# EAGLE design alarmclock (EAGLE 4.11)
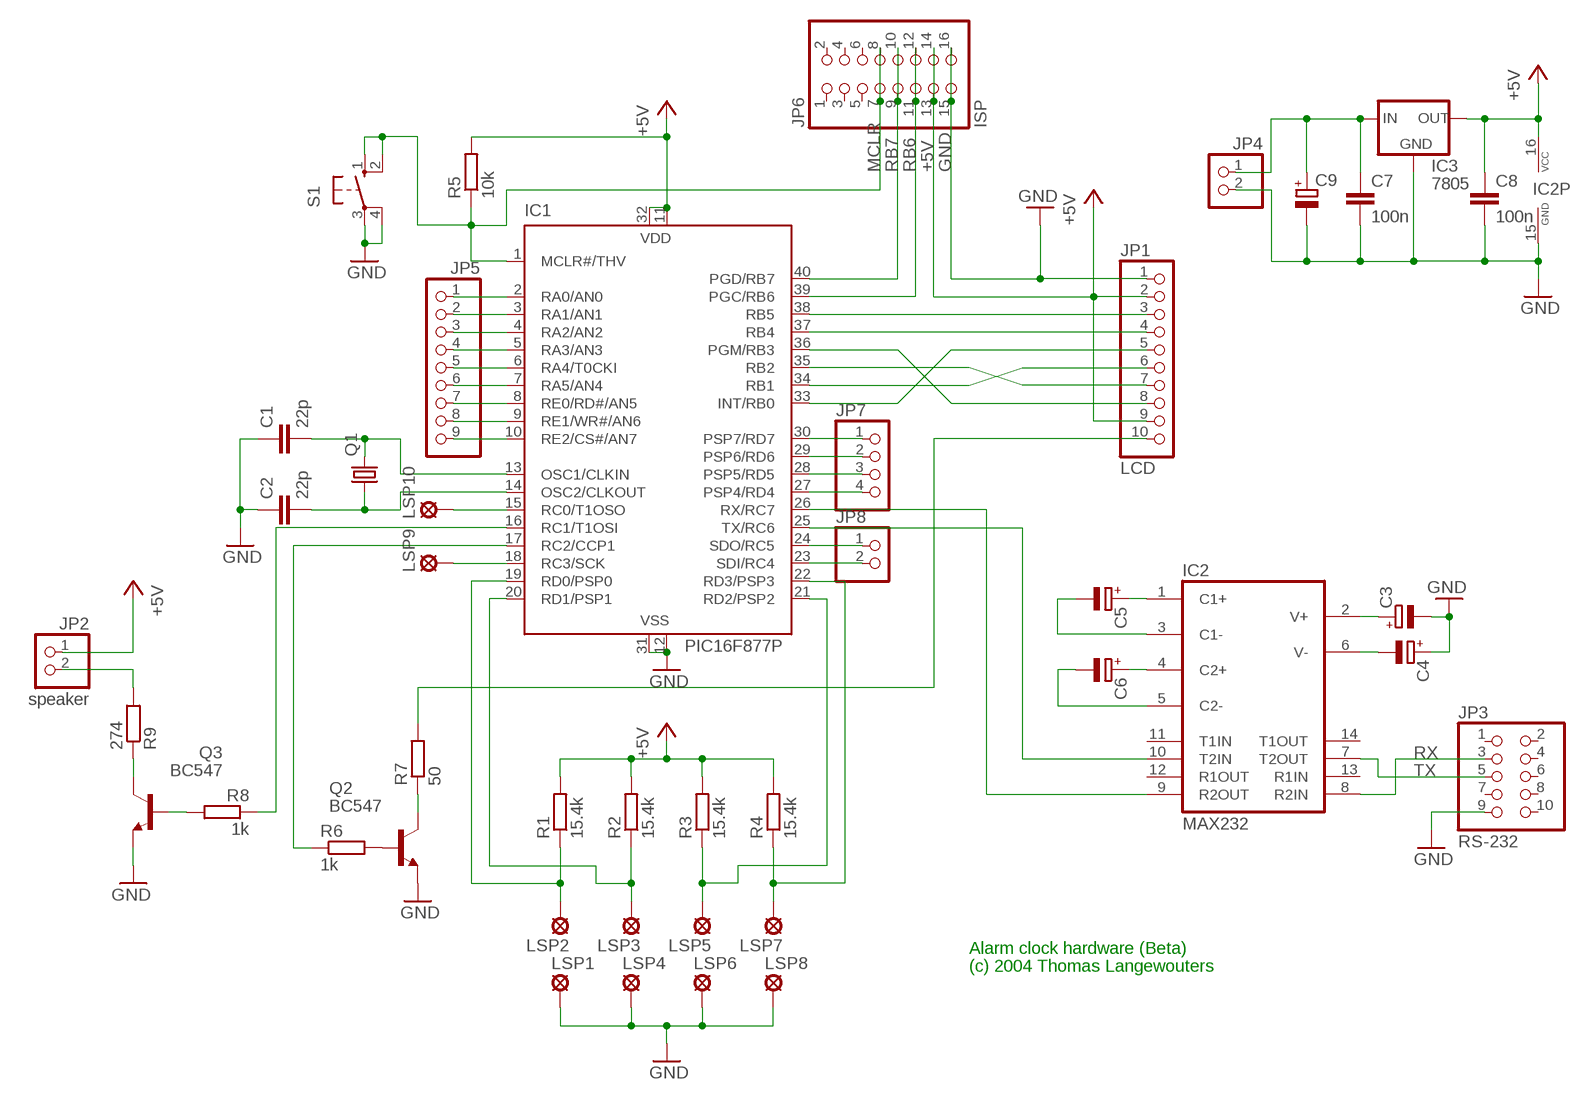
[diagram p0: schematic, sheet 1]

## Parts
C1  22p  C-EU050-025X075  [C050-025X075]
C2  22p  C-EU050-025X075  [C050-025X075]
C3  CPOL-EUE5-5  [E5-5]
C4  CPOL-EUE5-5  [E5-5]
C5  CPOL-EUE5-5  [E5-5]
C6  CPOL-EUE5-5  [E5-5]
C7  100n  C-EU050-030X075  [C050-030X075]
C8  100n  C-EU050-030X075  [C050-030X075]
C9  CPOL-EUE5-10.5  [E5-10,5]
IC1  PIC16F877P  [DIL40]
IC2  MAX232  [DIL16]
IC3  7805  78XXS  [78XXS]
JP1  LCD  PINHD-1X10  [1X10]
JP2  speaker  PINHD-1X2  [1X02]
JP3  RS-232  PINHD-2X5  [2X05]
JP4  PINHD-1X2  [1X02]
JP5  PINHD-1X9  [1X09]
JP6  ISP  PINHD-2X8  [2X08]
JP7  PINHD-1X4  [1X04]
JP8  PINHD-1X2  [1X02]
LSP1  SE11  [SE11]
LSP2  SE11  [SE11]
LSP3  SE11  [SE11]
LSP4  SE11  [SE11]
LSP5  SE11  [SE11]
LSP6  SE11  [SE11]
LSP7  SE11  [SE11]
LSP8  SE11  [SE11]
LSP9  SE11  [SE11]
LSP10  SE11  [SE11]
Q1  CRYTALHC49S  [HC49/S]
Q2  BC547  [TO92]
Q3  BC547  [TO92]
R1  15.4k  R-EU_0207/10  [0207/10]
R2  15.4k  R-EU_0207/10  [0207/10]
R3  15.4k  R-EU_0207/10  [0207/10]
R4  15.4k  R-EU_0207/10  [0207/10]
R5  10k  R-EU_0207/10  [0207/10]
R6  1k  R-EU_0207/10  [0207/10]
R7  50  R-EU_0207/10  [0207/10]
R8  1k  R-EU_0207/10  [0207/10]
R9  274  R-EU_0207/10  [0207/10]
S1  10-XX  [B3F-10XX]

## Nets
+5V: C8.1 IC1.11(VDD) IC1.32(VDD) IC2.16(VCC) IC3.OUT JP1.2 JP1.9 JP2.1 JP6.13 JP6.14 R1.2 R2.2 R3.2 R4.2 R5.2
GND: C1.1 C2.1 C3.- C4.+ C7.2 C8.2 C9.- IC1.12(VSS) IC1.31(VSS) IC2.15(GND) IC3.GND JP1.1 JP3.9 JP4.2 JP6.15 JP6.16 LSP1.MP LSP4.MP LSP6.MP LSP8.MP Q2.1(E) Q3.1(E) S1.3(P) S1.4(P1)
MCLR: IC1.1(MCLR#/THV) JP6.7 JP6.8 R5.1 S1.1(S) S1.2(S1)
N$1: C1.2 IC1.13(OSC1/CLKIN) Q1.2
N$3: IC1.36(PGM/RB3) JP1.8
N$4: IC1.19(RD0/PSP0) LSP2.MP R1.1
N$5: IC1.20(RD1/PSP1) LSP3.MP R2.1
N$6: IC1.21(RD2/PSP2) LSP5.MP R3.1
N$7: IC1.22(RD3/PSP3) LSP7.MP R4.1
N$8: IC1.33(INT/RB0) JP1.5
N$9: IC1.34(RB1) JP1.6
N$10: IC1.35(RB2) JP1.7
N$11: IC1.25(TX/RC6) IC2.10(T2IN)
N$12: IC1.26(RX/RC7) IC2.9(R2OUT)
N$13: C6.- IC2.5(C2-)
N$14: IC1.17(RC2/CCP1) R6.1
N$15: JP1.10 R7.2
N$16: IC1.38(RB5) JP1.3
N$17: IC1.37(RB4) JP1.4
N$18: Q2.3(C) R7.1
N$19: Q2.2(B) R6.2
N$20: IC1.16(RC1/T1OSI) R8.1
N$21: Q3.2(B) R8.2
N$22: Q3.3(C) R9.1
N$23: JP2.2 R9.2
N$24: C6.+ IC2.4(C2+)
N$25: C5.- IC2.3(C1-)
N$26: C5.+ IC2.1(C1+)
N$27: C4.- IC2.6(V-)
N$28: C3.+ IC2.2(V+)
N$29: C7.1 C9.+ IC3.IN JP4.1
N$32: IC1.2(RA0/AN0) JP5.1
N$33: IC1.3(RA1/AN1) JP5.2
N$34: IC1.4(RA2/AN2) JP5.3
N$35: IC1.5(RA3/AN3) JP5.4
N$36: IC1.6(RA4/T0CKI) JP5.5
N$37: IC1.7(RA5/AN4) JP5.6
N$38: IC1.8(RE0/RD#/AN5) JP5.7
N$39: IC1.9(RE1/WR#/AN6) JP5.8
N$40: IC1.10(RE2/CS#/AN7) JP5.9
N$41: IC1.30(PSP7/RD7) JP7.1
N$42: IC1.29(PSP6/RD6) JP7.2
N$43: IC1.28(PSP5/RD5) JP7.3
N$44: IC1.27(PSP4/RD4) JP7.4
N$45: IC1.24(SDO/RC5) JP8.1
N$46: IC1.23(SDI/RC4) JP8.2
N$47: C2.2 IC1.14(OSC2/CLKOUT) Q1.1
N$52: IC1.15(RC0/T1OSO) LSP10.MP
N$53: IC1.18(RC3/SCK) LSP9.MP
RB6: IC1.39(PGC/RB6) JP6.11 JP6.12
RB7: IC1.40(PGD/RB7) JP6.9 JP6.10
RX: IC2.8(R2IN) JP3.3
TX: IC2.7(T2OUT) JP3.5
Unconnected: IC2.11(T1IN) IC2.12(R1OUT) IC2.13(R1IN) IC2.14(T1OUT) JP3.1 JP3.2 JP3.4 JP3.6 JP3.7 JP3.8 JP3.10 JP6.1 JP6.2 JP6.3 JP6.4 JP6.5 JP6.6

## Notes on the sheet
- Alarm clock hardware (Beta)
- (c) 2004 Thomas Langewouters

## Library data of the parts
C1 C2 C7 C8 = rcl:C-EU: CAPACITOR, European symbol
C3-C6 C9 = rcl:CPOL-EU: POLARIZED CAPACITOR, European symbol
IC1 = microchip:PIC16F87*: MICROCONTROLLER
IC2 = maxim:MAX232: RS232 TRANSEIVER
IC3 = v-reg:78XXS: VOLTAGE REGULATOR
JP1 = pinhead:PINHD-1X10: PIN HEADER
JP2 JP4 JP8 = pinhead:PINHD-1X2: PIN HEADER
JP3 = pinhead:PINHD-2X5: PIN HEADER
JP5 = pinhead:PINHD-1X9: PIN HEADER
JP6 = pinhead:PINHD-2X8: PIN HEADER
JP7 = pinhead:PINHD-1X4: PIN HEADER
LSP1-LSP10 = solpad:SE11: SOLDER PAD
Q1 = crystal:CRYTAL: CRYSTAL
Q2 Q3 = transistor-npn:BC547*: NPN Transistor
R1-R9 = rcl:R-EU_: RESISTOR, European symbol
S1 = switch-omron:10-XX: OMRON SWITCH

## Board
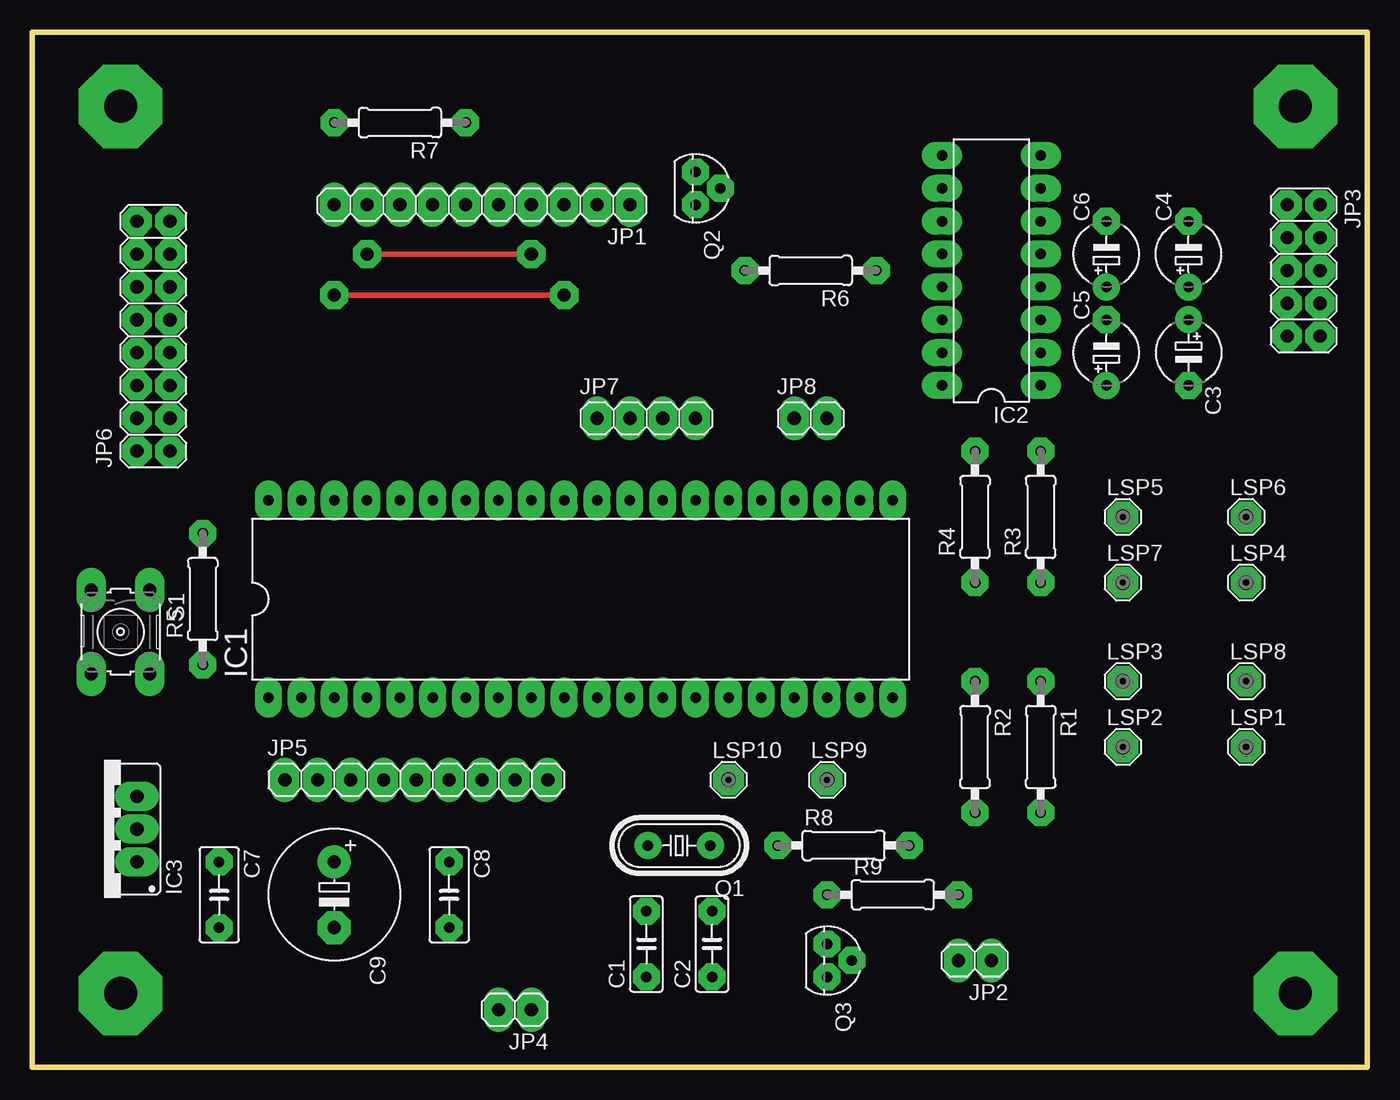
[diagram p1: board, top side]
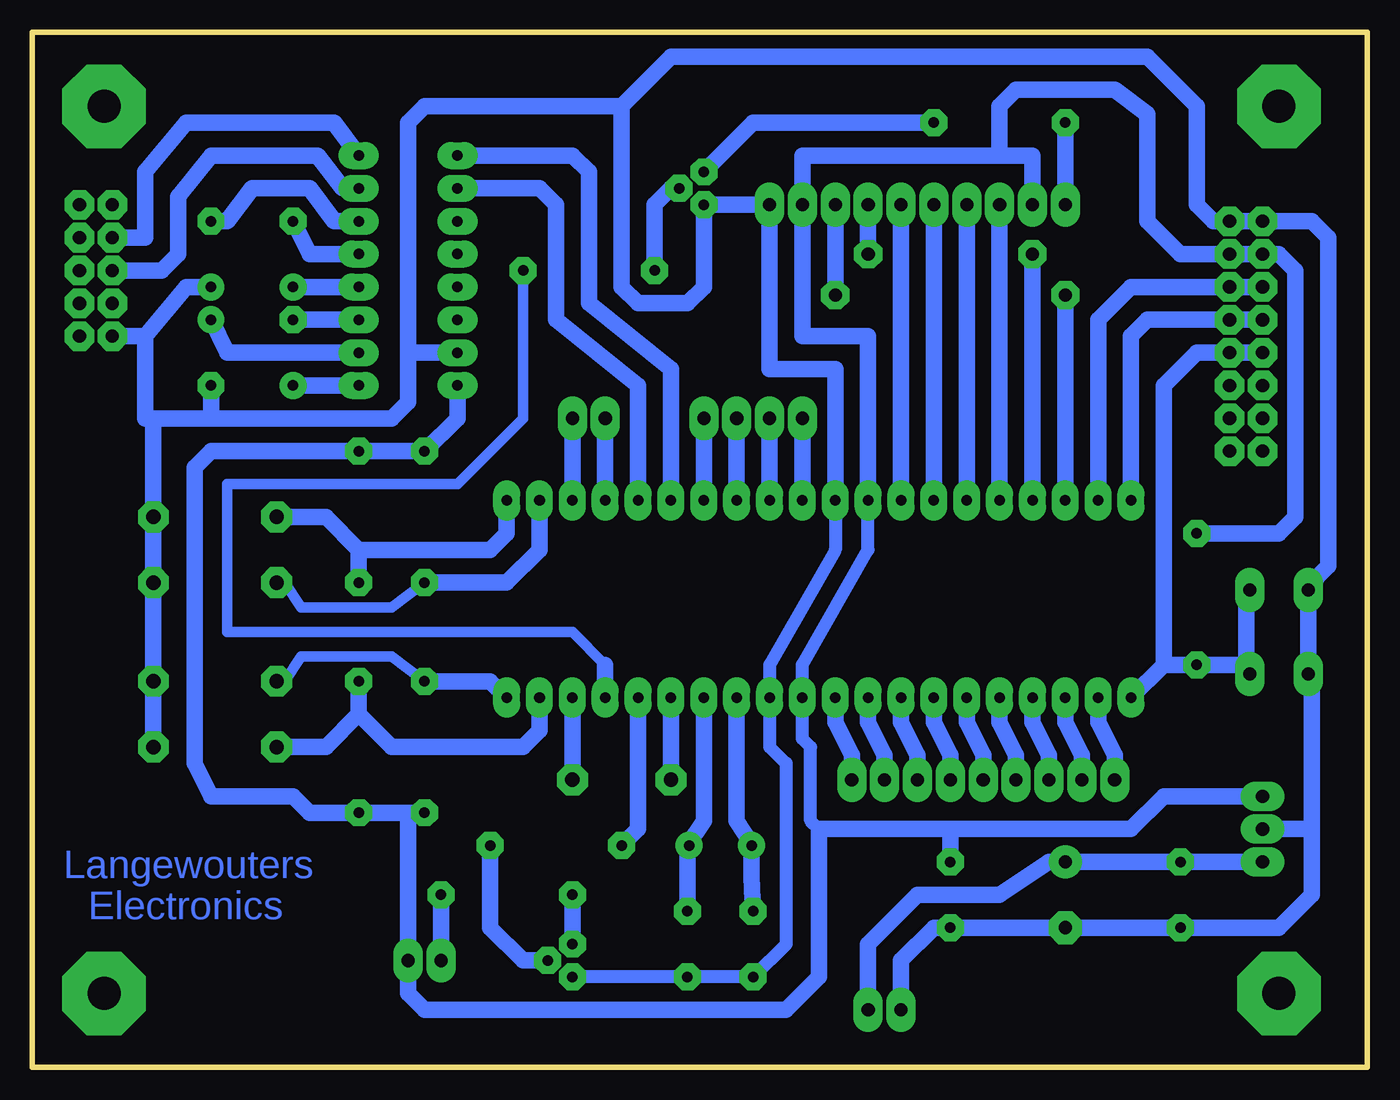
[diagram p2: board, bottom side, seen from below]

Size 103.17 x 80 mm. Coordinates in mm from the lower left corner, seen from the top.
Outline: 0,0 103.17,0 103.17,80 0,80 0,0
Copper layers (1*16): Top 0.035mm / dielectric 1.5mm / Bottom 0.035mm
Design rules "default": minimum track width 10mil, minimum drill 24mil, track to track 10mil, track to pad 8mil, pad to pad 8mil, via to via 8mil, smd to smd 8mil, copper to edge 40mil, drill to drill 8mil, minimum pad ring 15mil, minimum via ring 15mil, stop-mask expansion 4mil, vias tented up to drill 0mil, thermal gap 10mil

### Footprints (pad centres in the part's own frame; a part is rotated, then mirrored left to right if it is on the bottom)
C050-025X075 = drill 0.813 octagon: 1 -2.54,0; 2 2.54,0
E5-5 = drill 0.813 pad 1.905 round: + -2.54,0 | drill 0.813 pad 1.905 octagon: - 2.54,0
C050-030X075 = drill 0.813 octagon: 1 -2.54,0; 2 2.54,0
E5-10,5 = drill 1.016 pad 2.54 round: + -2.54,0 | drill 1.016 pad 2.54 octagon: - 2.54,0
DIL40 = drill 0.813 long: 1 -24.13,-7.62; 2 -21.59,-7.62; 3 -19.05,-7.62; 4 -16.51,-7.62; 5 -13.97,-7.62; 6 -11.43,-7.62; 7 -8.89,-7.62; 8 -6.35,-7.62; 9 -3.81,-7.62; 10 -1.27,-7.62; 11 1.27,-7.62; 12 3.81,-7.62; 13 6.35,-7.62; 14 8.89,-7.62; 15 11.43,-7.62; 16 13.97,-7.62; 17 16.51,-7.62; 18 19.05,-7.62; 19 21.59,-7.62; 20 24.13,-7.62; 21 24.13,7.62; 22 21.59,7.62; 23 19.05,7.62; 24 16.51,7.62; 25 13.97,7.62; 26 11.43,7.62; 27 8.89,7.62; 28 6.35,7.62; 29 3.81,7.62; 30 1.27,7.62; 31 -1.27,7.62; 32 -3.81,7.62; 33 -6.35,7.62; 34 -8.89,7.62; 35 -11.43,7.62; 36 -13.97,7.62; 37 -16.51,7.62; 38 -19.05,7.62; 39 -21.59,7.62; 40 -24.13,7.62
DIL16 = drill 0.813 long: 1 -8.89,-3.81; 2 -6.35,-3.81; 3 -3.81,-3.81; 4 -1.27,-3.81; 5 1.27,-3.81; 6 3.81,-3.81; 7 6.35,-3.81; 8 8.89,-3.81; 9 8.89,3.81; 10 6.35,3.81; 11 3.81,3.81; 12 1.27,3.81; 13 -1.27,3.81; 14 -3.81,3.81; 15 -6.35,3.81; 16 -8.89,3.81
78XXS = drill 1.016 long: GND 0,-2.54; IN -2.54,-2.54; OUT 2.54,-2.54
1X10 = drill 1.016 long: 1 -11.43,0; 2 -8.89,0; 3 -6.35,0; 4 -3.81,0; 5 -1.27,0; 6 1.27,0; 7 3.81,0; 8 6.35,0; 9 8.89,0; 10 11.43,0
1X02 = drill 1.016 long: 1 -1.27,0; 2 1.27,0
2X05 = drill 1.016 octagon: 1 -5.08,-1.27; 2 -5.08,1.27; 3 -2.54,-1.27; 4 -2.54,1.27; 5 0,-1.27; 6 0,1.27; 7 2.54,-1.27; 8 2.54,1.27; 9 5.08,-1.27; 10 5.08,1.27
1X09 = drill 1.016 long: 1 -10.16,0; 2 -7.62,0; 3 -5.08,0; 4 -2.54,0; 5 0,0; 6 2.54,0; 7 5.08,0; 8 7.62,0; 9 10.16,0
2X08 = drill 1.016 octagon: 1 -8.89,-1.27; 2 -8.89,1.27; 3 -6.35,-1.27; 4 -6.35,1.27; 5 -3.81,-1.27; 6 -3.81,1.27; 7 -1.27,-1.27; 8 -1.27,1.27; 9 1.27,-1.27; 10 1.27,1.27; 11 3.81,-1.27; 12 3.81,1.27; 13 6.35,-1.27; 14 6.35,1.27; 15 8.89,-1.27; 16 8.89,1.27
1X04 = drill 1.016 long: 1 -3.81,0; 2 -1.27,0; 3 1.27,0; 4 3.81,0
SE11 = drill 1.118 pad 2.159 octagon: MP 0,0
HC49/S = drill 0.813 round: 1 -2.413,0; 2 2.413,0
TO92 = drill 0.813 octagon: 1 1.27,0; 2 0,1.905; 3 -1.27,0
0207/10 = drill 0.813 octagon: 1 -5.08,0; 2 5.08,0
B3F-10XX = drill 1.016 long: 1 -3.251,2.261; 2 3.251,2.261; 3 -3.251,-2.261; 4 3.251,-2.261

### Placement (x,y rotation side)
C1  47.46,9.52 90 top
C2  52.54,9.52 90 top
C3  89.37,55.24 270 top
C4  89.37,62.86 90 top
C5  83.02,55.24 90 top
C6  83.02,62.86 90 top
C7  14.44,13.33 270 top
C8  32.22,13.33 270 top
C9  23.33,13.33 270 top
IC1  42.38,36.19 0 top
IC2  74.13,61.59 90 top
IC3  5.55,18.41 90 top
JP1  34.76,66.67 180 top
JP2  72.86,8.25 180 top
JP3  98.26,61.59 270 top
JP4  37.3,4.44 180 top
JP5  29.68,22.22 0 top
JP6  9.36,56.51 90 top
JP7  47.46,50.16 0 top
JP8  60.16,50.16 0 top
LSP1  93.81,24.76 0 top
LSP2  84.29,24.76 0 top
LSP3  84.29,29.84 0 top
LSP4  93.81,37.46 0 top
LSP5  84.29,42.54 0 top
LSP6  93.81,42.54 0 top
LSP7  84.29,37.46 0 top
LSP8  93.81,29.84 0 top
LSP9  61.43,22.22 0 top
LSP10  53.81,22.22 0 top
Q1  50,17.14 180 top
Q2  51.27,67.94 270 top
Q3  61.43,8.25 270 top
R1  77.94,24.76 270 top
R2  72.86,24.76 270 top
R3  77.94,42.54 90 top
R4  72.86,42.54 90 top
R5  13.17,36.19 90 top
R6  60.16,61.59 180 top
R7  28.41,73.02 180 top
R8  62.7,17.14 0 top
R9  66.51,13.33 0 top
S1  6.82,33.65 270 top

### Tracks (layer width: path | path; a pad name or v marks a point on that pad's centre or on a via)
+5V
  Bottom 1.016: IC1.32 38.57,40 43.65,31.11 IC1.11 43.65,25.39 43.02,24.76 43.02,19.04 42.38,18.41
  Bottom 1.27: 74.13,19.68 R2.2 | IC1.32 38.57,56.51 43.65,56.51 JP1.2 43.65,70.48 28.41,70.48 | JP1.9 25.87,70.48 28.41,70.48 | R5.2 6.82,41.27 5.55,42.54 5.55,61.59 6.82,62.86 JP6.14 JP6.13 14.44,62.86 16.98,65.4 16.98,73.66 19.52,75.56 27.14,75.56 28.41,74.29 28.41,70.48 | 74.13,19.68 JP2.1 74.13,5.71 72.86,4.44 44.92,4.44 42.38,6.98 42.38,18.41 32.22,18.41 | 74.13,19.68 R1.2 81.75,19.68 83.02,20.95 89.37,20.95 90.64,23.49 90.64,46.35 89.37,47.62 R3.2 R4.2 70.32,50.16 IC2.16 | IC3.OUT 15.71,20.95 18.25,18.41 32.22,18.41 | 32.22,18.41 C8.1
GND
  Bottom 0.406: S1.3 4.56,37.18 | 4.56,30.12 S1.4 | C7.2 15.71,10.79
  Bottom 1.016: Q3.1 C2.1 C1.1 44.92,9.52 44.92,23.49 46.19,24.76 IC1.12 46.19,31.11 41.11,40 IC1.31
  Bottom 1.27: LSP1.MP LSP8.MP LSP4.MP LSP6.MP 93.81,50.16 94.45,50.16 | IC1.31 41.11,53.97 46.19,53.97 JP1.1 Q2.1 51.27,60.32 52.54,59.05 56.35,59.05 57.62,60.32 57.62,74.29 | 57.62,74.29 53.81,78.1 16.98,78.1 13.17,74.29 13.17,66.67 11.9,65.4 JP6.15 JP6.16 4.28,65.4 3.01,64.13 3.01,38.73 4.56,37.18 | S1.4 S1.3 | 4.56,30.12 4.28,29.2 4.28,18.41 | 74.13,55.24 74.13,51.43 75.4,50.16 89.37,50.16 | 89.37,50.16 94.45,50.16 | 94.45,56.51 91.27,60.32 C4.+ | 94.45,50.16 94.45,56.51 | 94.45,56.51 JP3.9 | 89.37,50.16 C3.- | 4.28,18.41 IC3.GND | 4.28,18.41 4.28,13.33 6.82,10.79 C7.2 C9.- C8.2 33.49,10.79 36.03,8.25 JP4.2 | 74.13,55.24 IC2.15 | 74.13,55.24 74.13,73.02 72.86,74.29 57.62,74.29
MCLR
  Bottom 0.406: S1.2 9.36,30.4 9.36,31.11 | 9.36,36.9 S1.1
  Bottom 1.27: 15.71,31.11 IC1.1 | 15.71,31.11 R5.1 9.36,31.11 9.36,36.9 | 15.71,31.11 15.71,52.7 13.17,55.24 JP6.7 JP6.8
N$1
  Bottom 1.27: IC1.13 48.73,19.04 47.59,17.27 Q1.2 47.59,14.73 C1.2
N$3
  Bottom 1.27: IC1.36 JP1.8
N$4
  Bottom 1.27: 77.94,27.3 80.48,24.76 LSP2.MP | 77.94,27.3 75.4,24.76 65.24,24.76 63.97,26.03 IC1.19 | 77.94,27.3 R1.1
N$5
  Bottom 0.813: R2.1 75.4,31.74 82.38,31.74 83.66,29.84 LSP3.MP
  Bottom 1.27: IC1.20 67.78,29.84 R2.1
N$6
  Bottom 1.27: IC1.21 66.51,41.27 67.78,40 77.94,40 | 77.94,40 R3.1 | 77.94,40 80.48,42.54 LSP5.MP
N$7
  Bottom 0.813: LSP7.MP 83.66,37.46 82.38,35.55 75.4,35.55 R4.1
  Bottom 1.27: R4.1 66.51,37.46 63.97,40 IC1.22
N$8
  Bottom 1.27: IC1.33 JP1.5
N$9
  Bottom 1.27: IC1.34 JP1.6
N$10
  Bottom 1.27: IC1.35 JP1.7
N$11
  Bottom 1.27: IC1.25 56.35,52.7 62.7,57.78 62.7,66.67 63.97,67.94 IC2.10
N$12
  Bottom 1.27: IC1.26 53.81,53.97 60.16,59.05 60.16,69.21 61.43,70.48 IC2.9
N$13
  Bottom 1.27: IC2.5 81.75,62.86 C6.-
N$14
  Bottom 0.813: 58.89,31.11 61.43,33.65 88.1,33.65 88.1,45.08 70.32,45.08 65.24,50.16 R6.1
  Bottom 1.27: IC1.17 58.89,31.11
N$15
  Bottom 1.27: JP1.10 R7.2
N$16  (via drill 1.02 pad 2.18)
  Top 0.406: v23.33,59.69 v41.11,59.69
  Bottom 1.27: IC1.38 v23.33,59.69 | v41.11,59.69 JP1.3
N$17  (via drill 1.02 pad 2.18)
  Top 0.406: v25.87,62.86 v38.57,62.86
  Bottom 1.27: v38.57,62.86 JP1.4 | IC1.37 v25.87,62.86
N$18
  Bottom 1.27: R7.1 47.46,73.02 Q2.3
N$19
  Bottom 1.27: Q2.2 53.81,67.94 55.08,66.67 R6.2
N$20
  Bottom 1.27: R8.1 56.35,18.41 IC1.16
N$21
  Bottom 1.27: Q3.2 65.24,8.25 67.78,10.79 R8.2
N$22
  Bottom 1.27: Q3.3 R9.1
N$23
  Bottom 1.27: JP2.2 R9.2
N$24
  Bottom 1.27: IC2.4 C6.+
N$25
  Bottom 1.27: IC2.3 C5.-
N$26
  Bottom 1.27: IC2.1 C5.+
N$27
  Bottom 1.27: IC2.6 79.84,65.4 81.75,67.94 86.19,67.94 88.1,65.4 C4.-
N$28
  Bottom 1.27: C3.+ 88.1,55.24 IC2.2
N$29
  Bottom 1.27: IC3.IN C7.1 C9.+ 24.6,15.87 28.41,13.33 34.76,13.33 38.57,9.52 JP4.1
N$30  (via drill 2.54 pad 6.45)
  other vias: 97.62,74.29
N$32
  Bottom 1.27: JP5.1 19.52,24.12 20.79,26.66 IC1.2
N$33
  Bottom 1.27: JP5.2 22.06,24.12 23.33,26.66 IC1.3
N$34
  Bottom 1.27: JP5.3 24.6,24.12 25.87,26.66 IC1.4
N$35
  Bottom 1.27: JP5.4 27.14,24.12 28.41,26.66 IC1.5
N$36
  Bottom 1.27: JP5.5 29.68,24.12 30.95,26.66 IC1.6
N$37
  Bottom 1.27: JP5.6 32.22,24.12 33.49,26.66 IC1.7
N$38
  Bottom 1.27: JP5.7 34.76,24.12 36.03,26.66 IC1.8
N$39
  Bottom 1.27: JP5.8 37.3,24.12 38.57,26.66 IC1.9
N$40
  Bottom 1.27: JP5.9 39.84,24.12 41.11,26.66 IC1.10
N$41
  Bottom 1.27: IC1.30 JP7.1
N$42
  Bottom 1.27: IC1.29 JP7.2
N$43
  Bottom 1.27: IC1.28 JP7.3
N$44
  Bottom 1.27: IC1.27 JP7.4
N$45
  Bottom 1.27: IC1.24 JP8.1
N$46
  Bottom 1.27: IC1.23 JP8.2
N$47
  Bottom 1.27: IC1.14 51.27,19.04 52.54,17.14 | C2.2 52.54,17.14 | 52.54,17.14 Q1.1
N$48  (via drill 2.54 pad 6.45)
  other vias: 6.82,5.71
N$50  (via drill 2.54 pad 6.45)
  other vias: 6.82,74.29
N$51  (via drill 2.54 pad 6.45)
  other vias: 97.62,5.71
N$52
  Bottom 1.27: LSP10.MP IC1.15
N$53
  Bottom 1.27: LSP9.MP IC1.18
RB6
  Bottom 1.27: IC1.39 20.79,57.78 18.25,60.32 JP6.11 JP6.12
RB7
  Bottom 1.27: IC1.40 18.25,56.51 16.98,57.78 JP6.9 JP6.10
RX
  Bottom 1.27: IC2.8 79.84,73.02 91.27,73.02 94.45,69.21 94.45,64.13 JP3.3
TX
  Bottom 1.27: IC2.7 79.21,67.94 81.11,70.48 89.37,70.48 91.91,67.3 91.91,62.86 93.18,61.59 JP3.5

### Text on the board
Bottom: Langewouters | Electronics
